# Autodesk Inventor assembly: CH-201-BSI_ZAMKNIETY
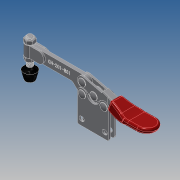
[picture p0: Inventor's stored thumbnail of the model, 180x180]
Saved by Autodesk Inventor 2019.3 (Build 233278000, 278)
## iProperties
Company: ·L?¤¤?
Created: 2010-06
Part Number: CH-201-BSI_ZAMKNIETY
Material: Ogólny
Description: STEP AP203
Document SubType Name: Assembly
Designer: CADENGINEERING4
Sending System: SolidWorks 2005179
Preprocessor: SwSTEP 2.0
Title: CH-201-BSI.STEP
Author: ·L?¥Î?
Revision Number: ANY
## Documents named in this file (9)
- E:\STRONA\Horizontal toggle clamp\CH-201-BSI\CH-201-BSI_ZAMKNIETY.iam
- E:\STRONA\Horizontal toggle clamp\CH-201-BSI\14134-02___.ipt
- E:\STRONA\Horizontal toggle clamp\CH-201-BSI\201-B-06___.ipt
- E:\STRONA\Horizontal toggle clamp\CH-201-BSI\201-B-04___.ipt
- E:\STRONA\Horizontal toggle clamp\CH-201-BSI\BR-142___.ipt
- E:\STRONA\Horizontal toggle clamp\CH-201-BSI\201-B___.iam
- E:\STRONA\Horizontal toggle clamp\CH-201-BSI\201-BSI-02___.ipt
- E:\STRONA\Horizontal toggle clamp\CH-201-BSI\201-BI-01___.ipt
- E:\STRONA\Horizontal toggle clamp\CH-201-BSI\14134___.ipt
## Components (13 placed, 13 different names)
1. 14134-02_??_1 — Zestawiające:4, Zestawiające:6, Równoległe:2
2. 14134-02_??_2 — Zestawiające:5, Zestawiające:7
3. 201-B-06_??_3 — Zestawiające:21, Zestawiające:22, Zestawiające:25
4. 201-B-06_??_4 — Zestawiające:11, Zestawiające:12, Zestawiające:15
5. 201-B-04_??_5 — Zestawiające:8, Zestawiające:9, Zestawiające:10
6. BR-142_??_6 — Zestawiające:2, Równoległe:1, Zestawiające:3, Zestawiające:6, Zestawiające:7
7. 201-B-04_??_7 — Zestawiające:8, Zestawiające:9, Zestawiające:10, Zestawiające:15, Zestawiające:16, Zestawiające:17, Zestawiające:18, Zestawiające:19
8. 201-B_??_8 [sub-assembly] — Zestawiające:18, Zestawiające:19, Zestawiające:20, Zestawiające:21, Zestawiające:22, Przejściowe:1
9. 201-BSI-02_??_9 — Zestawiające:1, Zestawiające:2, Równoległe:1, Zestawiające:23, Zestawiające:24, Zestawiające:25
10. 201-B-06_??_10 — Zestawiające:17, Zestawiające:20
11. 201-BI-01_??_11 — Zestawiające:11, Zestawiające:12, Zestawiające:13, Zestawiające:14, Zestawiające:16, Zestawiające:24, Przejściowe:1
12. 14134_??_12 — Zestawiające:1, Zestawiające:3, Zestawiające:4, Zestawiające:5, Równoległe:2
13. 201-B-06_??_13 — Zestawiające:13, Zestawiające:14, Zestawiające:23
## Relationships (28: Mate 25, Flush 2, Transitional 1)
- Zestawiające:1 [Mate]: 201-BSI-02_??_9 ↔ 14134_??_12
- Zestawiające:2 [Mate]: BR-142_??_6 ↔ 201-BSI-02_??_9
- Równoległe:1 [Flush]: BR-142_??_6 ↔ 201-BSI-02_??_9
- Zestawiające:3 [Mate]: BR-142_??_6 ↔ 14134_??_12
- Zestawiające:4 [Mate]: 14134-02_??_1 ↔ 14134_??_12
- Zestawiające:5 [Mate]: 14134-02_??_2 ↔ 14134_??_12
- Zestawiające:6 [Mate]: 14134-02_??_1 ↔ BR-142_??_6
- Równoległe:2 [Flush]: 14134-02_??_1 ↔ 14134_??_12
- Zestawiające:7 [Mate]: 14134-02_??_2 ↔ BR-142_??_6
- Zestawiające:8 [Mate]: 201-B-04_??_5 ↔ 201-B-04_??_7
- Zestawiające:9 [Mate]: 201-B-04_??_5 ↔ 201-B-04_??_7
- Zestawiające:10 [Mate]: 201-B-04_??_5 ↔ 201-B-04_??_7
- Zestawiające:11 [Mate]: 201-B-06_??_4 ↔ 201-BI-01_??_11
- Zestawiające:12 [Mate]: 201-B-06_??_4 ↔ 201-BI-01_??_11
- Zestawiające:13 [Mate]: 201-BI-01_??_11 ↔ 201-B-06_??_13
- Zestawiające:14 [Mate]: 201-BI-01_??_11 ↔ 201-B-06_??_13
- Zestawiające:15 [Mate]: 201-B-06_??_4 ↔ 201-B-04_??_7
- Zestawiające:16 [Mate]: 201-B-04_??_7 ↔ 201-BI-01_??_11
- Zestawiające:17 [Mate]: 201-B-04_??_7 ↔ 201-B-06_??_10
- Zestawiające:18 [Mate]: 201-B-04_??_7 ↔ 201-B_??_8
- Zestawiające:19 [Mate]: 201-B-04_??_7 ↔ 201-B_??_8
- Zestawiające:20 [Mate]: 201-B_??_8 ↔ 201-B-06_??_10
- Zestawiające:21 [Mate]: 201-B-06_??_3 ↔ 201-B_??_8
- Zestawiające:22 [Mate]: 201-B-06_??_3 ↔ 201-B_??_8
- Zestawiające:23 [Mate]: 201-BSI-02_??_9 ↔ 201-B-06_??_13
- Zestawiające:24 [Mate]: 201-BSI-02_??_9 ↔ 201-BI-01_??_11
- Zestawiające:25 [Mate]: 201-B-06_??_3 ↔ 201-BSI-02_??_9
- Przejściowe:1 [Transitional]: 201-B_??_8 ↔ 201-BI-01_??_11
